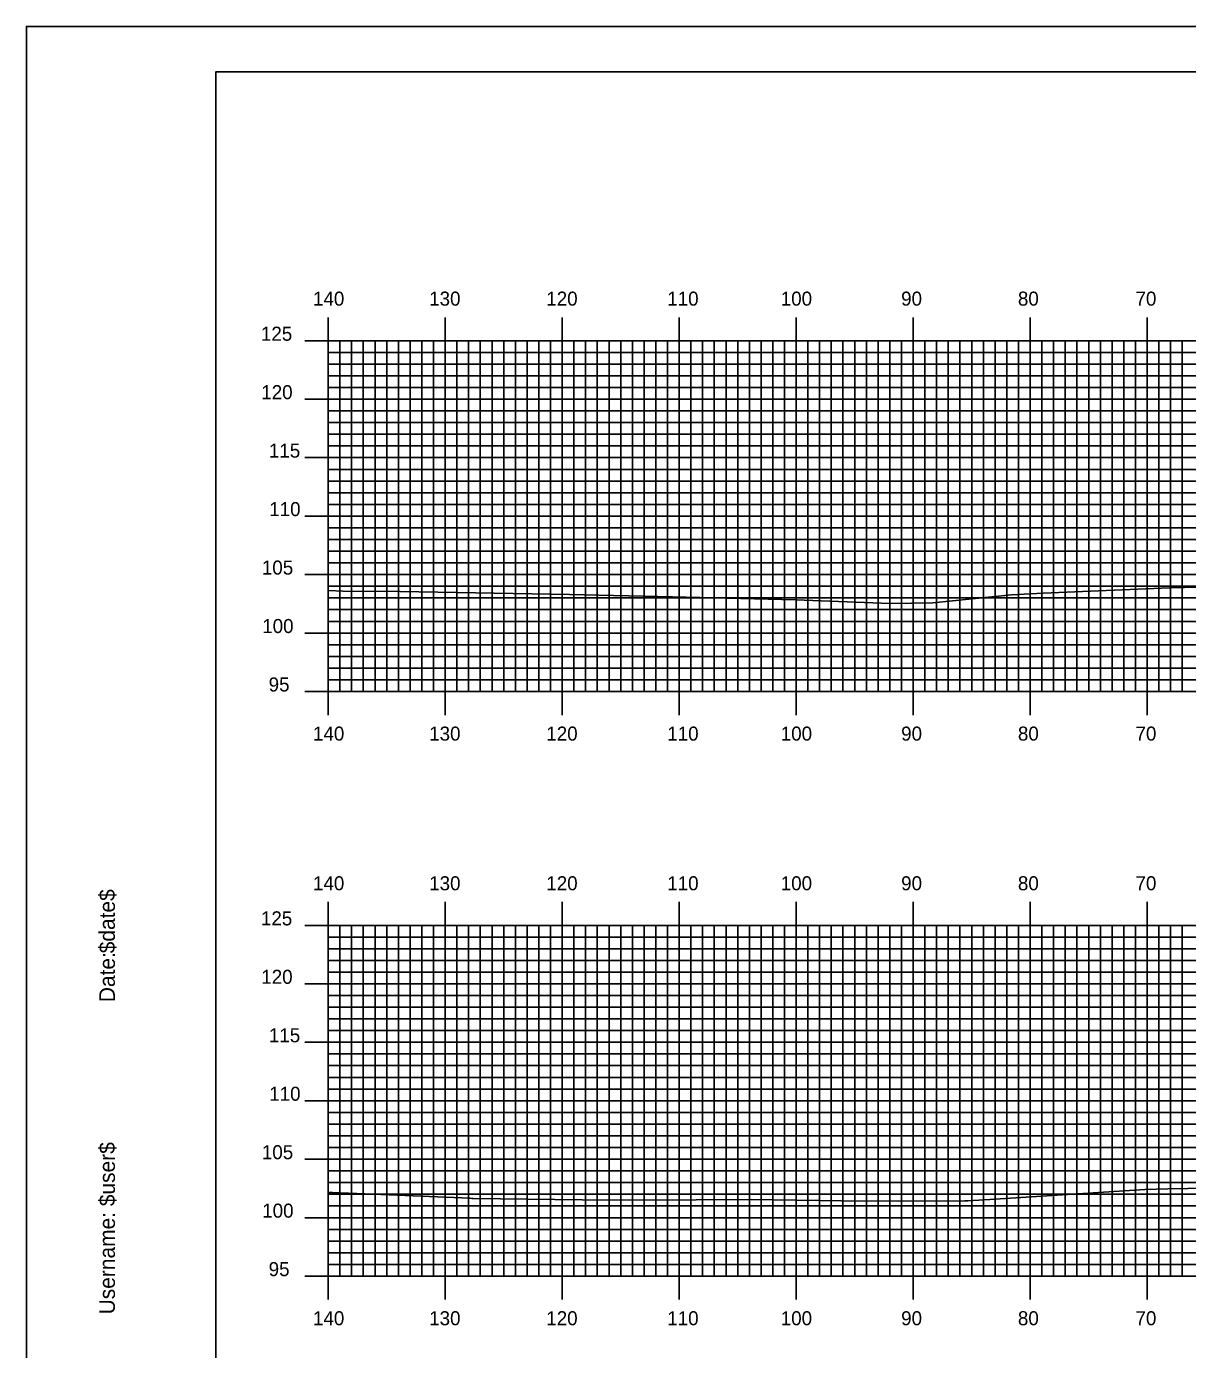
# Model space of a CAD drawing. Extents: x 1787763 to 1788106, y 442591 to 442811.
# Drawn here: x 1787762.8 to 1787862.1, y 442697.4 to 442810.5 of the extents above; entities that cross this region are included whole.
import ezdxf

# ---------------------------------------------------------------- set-up
doc = ezdxf.new("R2010")
doc.units = 0
for name, color, linetype in [('BORDER', 7, 'Continuous'), ('H_V ANNOTATION', 7, 'Continuous'), ('MAJOR', 7, 'Continuous'), ('MINOR', 7, 'Continuous'), ('PLOT BOUNDARY', 7, 'Continuous'), ('S_Roadway_Centerline', 7, 'Continuous')]:
    doc.layers.add(name, color=color, linetype=linetype)

msp = doc.modelspace()

# ---------------------------------------------------------------- linework, layer by layer
at = {"layer": 'BORDER'}
msp.add_lwpolyline([(1787779.02, 442596.67), (1788099.02, 442596.67), (1788099.02, 442806.67), (1787779.02, 442806.67)], close=True, dxfattribs=at)
at = {"layer": 'MAJOR'}
for p, q in [((1787788.62, 442785.67), (1787788.62, 442783.67)), ((1787798.62, 442785.67), (1787798.62, 442783.67)), ((1787808.62, 442785.67), (1787808.62, 442783.67)), ((1787818.62, 442785.67), (1787818.62, 442783.67)), ((1787828.62, 442785.67), (1787828.62, 442783.67)), ((1787838.62, 442785.67), (1787838.62, 442783.67)), ((1787848.62, 442785.67), (1787848.62, 442783.67)), ((1787858.62, 442785.67), (1787858.62, 442783.67)), ((1787786.61, 442783.67), (1787788.62, 442783.67)), ((1787788.62, 442783.67), (1788068.62, 442783.67)), ((1787788.62, 442753.67), (1787788.62, 442783.67)), ((1787788.62, 442753.67), (1787788.62, 442783.67)), ((1787788.62, 442783.67), (1788068.62, 442783.67)), ((1787798.62, 442753.67), (1787798.62, 442783.67)), ((1787808.62, 442753.67), (1787808.62, 442783.67)), ((1787818.62, 442753.67), (1787818.62, 442783.67)), ((1787828.62, 442753.67), (1787828.62, 442783.67)), ((1787838.62, 442753.67), (1787838.62, 442783.67)), ((1787848.62, 442753.67), (1787848.62, 442783.67)), ((1787858.62, 442753.67), (1787858.62, 442783.67)), ((1787786.61, 442778.67), (1787788.62, 442778.67)), ((1787788.62, 442778.67), (1788068.62, 442778.67)), ((1787786.61, 442773.67), (1787788.62, 442773.67)), ((1787788.62, 442773.67), (1788068.62, 442773.67)), ((1787786.61, 442768.67), (1787788.62, 442768.67)), ((1787788.62, 442768.67), (1788068.62, 442768.67)), ((1787786.61, 442763.67), (1787788.62, 442763.67)), ((1787788.62, 442763.67), (1788068.62, 442763.67)), ((1787786.61, 442758.67), (1787788.62, 442758.67)), ((1787788.62, 442758.67), (1788068.62, 442758.67)), ((1787786.61, 442753.67), (1787788.62, 442753.67)), ((1787788.62, 442753.67), (1788068.62, 442753.67)), ((1787788.62, 442753.67), (1788068.62, 442753.67)), ((1787788.62, 442751.66), (1787788.62, 442753.67)), ((1787798.62, 442751.66), (1787798.62, 442753.67)), ((1787808.62, 442751.66), (1787808.62, 442753.67)), ((1787818.62, 442751.66), (1787818.62, 442753.67)), ((1787828.62, 442751.66), (1787828.62, 442753.67)), ((1787838.62, 442751.66), (1787838.62, 442753.67)), ((1787848.62, 442751.66), (1787848.62, 442753.67)), ((1787858.62, 442751.66), (1787858.62, 442753.67)), ((1787788.62, 442735.67), (1787788.62, 442733.67)), ((1787798.62, 442735.67), (1787798.62, 442733.67)), ((1787808.62, 442735.67), (1787808.62, 442733.67)), ((1787818.62, 442735.67), (1787818.62, 442733.67)), ((1787828.62, 442735.67), (1787828.62, 442733.67)), ((1787838.62, 442735.67), (1787838.62, 442733.67)), ((1787848.62, 442735.67), (1787848.62, 442733.67)), ((1787858.62, 442735.67), (1787858.62, 442733.67)), ((1787786.61, 442733.67), (1787788.62, 442733.67)), ((1787788.62, 442733.67), (1788068.62, 442733.67)), ((1787788.62, 442703.67), (1787788.62, 442733.67)), ((1787788.62, 442703.67), (1787788.62, 442733.67)), ((1787788.62, 442733.67), (1788068.62, 442733.67)), ((1787798.62, 442703.67), (1787798.62, 442733.67)), ((1787808.62, 442703.67), (1787808.62, 442733.67)), ((1787818.62, 442703.67), (1787818.62, 442733.67)), ((1787828.62, 442703.67), (1787828.62, 442733.67)), ((1787838.62, 442703.67), (1787838.62, 442733.67)), ((1787848.62, 442703.67), (1787848.62, 442733.67)), ((1787858.62, 442703.67), (1787858.62, 442733.67)), ((1787786.61, 442728.67), (1787788.62, 442728.67)), ((1787788.62, 442728.67), (1788068.62, 442728.67)), ((1787786.61, 442723.67), (1787788.62, 442723.67)), ((1787788.62, 442723.67), (1788068.62, 442723.67)), ((1787786.61, 442718.67), (1787788.62, 442718.67)), ((1787788.62, 442718.67), (1788068.62, 442718.67)), ((1787786.61, 442713.67), (1787788.62, 442713.67)), ((1787788.62, 442713.67), (1788068.62, 442713.67)), ((1787786.61, 442708.67), (1787788.62, 442708.67)), ((1787788.62, 442708.67), (1788068.62, 442708.67)), ((1787786.61, 442703.67), (1787788.62, 442703.67)), ((1787788.62, 442703.67), (1788068.62, 442703.67)), ((1787788.62, 442703.67), (1788068.62, 442703.67)), ((1787788.62, 442701.66), (1787788.62, 442703.67)), ((1787798.62, 442701.66), (1787798.62, 442703.67)), ((1787808.62, 442701.66), (1787808.62, 442703.67)), ((1787818.62, 442701.66), (1787818.62, 442703.67)), ((1787828.62, 442701.66), (1787828.62, 442703.67)), ((1787838.62, 442701.66), (1787838.62, 442703.67)), ((1787848.62, 442701.66), (1787848.62, 442703.67)), ((1787858.62, 442701.66), (1787858.62, 442703.67))]:
    msp.add_line(p, q, dxfattribs=at)
at = {"layer": 'MINOR'}
for p, q in [((1787789.62, 442753.67), (1787789.62, 442783.67)), ((1787790.62, 442753.67), (1787790.62, 442783.67)), ((1787791.62, 442753.67), (1787791.62, 442783.67)), ((1787792.62, 442753.67), (1787792.62, 442783.67)), ((1787793.62, 442753.67), (1787793.62, 442783.67)), ((1787794.62, 442753.67), (1787794.62, 442783.67)), ((1787795.62, 442753.67), (1787795.62, 442783.67)), ((1787796.62, 442753.67), (1787796.62, 442783.67)), ((1787797.62, 442753.67), (1787797.62, 442783.67)), ((1787799.62, 442753.67), (1787799.62, 442783.67)), ((1787800.62, 442753.67), (1787800.62, 442783.67)), ((1787801.62, 442753.67), (1787801.62, 442783.67)), ((1787802.62, 442753.67), (1787802.62, 442783.67)), ((1787803.62, 442753.67), (1787803.62, 442783.67)), ((1787804.62, 442753.67), (1787804.62, 442783.67)), ((1787805.62, 442753.67), (1787805.62, 442783.67)), ((1787806.62, 442753.67), (1787806.62, 442783.67)), ((1787807.62, 442753.67), (1787807.62, 442783.67)), ((1787809.62, 442753.67), (1787809.62, 442783.67)), ((1787810.62, 442753.67), (1787810.62, 442783.67)), ((1787811.62, 442753.67), (1787811.62, 442783.67)), ((1787812.62, 442753.67), (1787812.62, 442783.67)), ((1787813.62, 442753.67), (1787813.62, 442783.67)), ((1787814.62, 442753.67), (1787814.62, 442783.67)), ((1787815.62, 442753.67), (1787815.62, 442783.67)), ((1787816.62, 442753.67), (1787816.62, 442783.67)), ((1787817.62, 442753.67), (1787817.62, 442783.67)), ((1787819.62, 442753.67), (1787819.62, 442783.67)), ((1787820.62, 442753.67), (1787820.62, 442783.67)), ((1787821.62, 442753.67), (1787821.62, 442783.67)), ((1787822.62, 442753.67), (1787822.62, 442783.67)), ((1787823.62, 442753.67), (1787823.62, 442783.67)), ((1787824.62, 442753.67), (1787824.62, 442783.67)), ((1787825.62, 442753.67), (1787825.62, 442783.67)), ((1787826.62, 442753.67), (1787826.62, 442783.67)), ((1787827.62, 442753.67), (1787827.62, 442783.67)), ((1787829.62, 442753.67), (1787829.62, 442783.67)), ((1787830.62, 442753.67), (1787830.62, 442783.67)), ((1787831.62, 442753.67), (1787831.62, 442783.67)), ((1787832.62, 442753.67), (1787832.62, 442783.67)), ((1787833.62, 442753.67), (1787833.62, 442783.67)), ((1787834.62, 442753.67), (1787834.62, 442783.67)), ((1787835.62, 442753.67), (1787835.62, 442783.67)), ((1787836.62, 442753.67), (1787836.62, 442783.67)), ((1787837.62, 442753.67), (1787837.62, 442783.67)), ((1787839.62, 442753.67), (1787839.62, 442783.67)), ((1787840.62, 442753.67), (1787840.62, 442783.67)), ((1787841.62, 442753.67), (1787841.62, 442783.67)), ((1787842.62, 442753.67), (1787842.62, 442783.67)), ((1787843.62, 442753.67), (1787843.62, 442783.67)), ((1787844.62, 442753.67), (1787844.62, 442783.67)), ((1787845.62, 442753.67), (1787845.62, 442783.67)), ((1787846.62, 442753.67), (1787846.62, 442783.67)), ((1787847.62, 442753.67), (1787847.62, 442783.67)), ((1787849.62, 442753.67), (1787849.62, 442783.67)), ((1787850.62, 442753.67), (1787850.62, 442783.67)), ((1787851.62, 442753.67), (1787851.62, 442783.67)), ((1787852.62, 442753.67), (1787852.62, 442783.67)), ((1787853.62, 442753.67), (1787853.62, 442783.67)), ((1787854.62, 442753.67), (1787854.62, 442783.67)), ((1787855.62, 442753.67), (1787855.62, 442783.67)), ((1787856.62, 442753.67), (1787856.62, 442783.67)), ((1787857.62, 442753.67), (1787857.62, 442783.67)), ((1787859.62, 442753.67), (1787859.62, 442783.67)), ((1787860.62, 442753.67), (1787860.62, 442783.67)), ((1787861.62, 442753.67), (1787861.62, 442783.67)), ((1787788.62, 442782.67), (1788068.62, 442782.67)), ((1787788.62, 442782.67), (1787790.62, 442782.67)), ((1787788.62, 442781.67), (1788068.62, 442781.67)), ((1787788.62, 442781.67), (1787790.62, 442781.67)), ((1787788.62, 442780.67), (1788068.62, 442780.67)), ((1787788.62, 442780.67), (1787790.62, 442780.67)), ((1787788.62, 442779.67), (1788068.62, 442779.67)), ((1787788.62, 442779.67), (1787790.62, 442779.67)), ((1787788.62, 442777.67), (1788068.62, 442777.67)), ((1787788.62, 442777.67), (1787790.62, 442777.67)), ((1787788.62, 442776.67), (1788068.62, 442776.67)), ((1787788.62, 442776.67), (1787790.62, 442776.67)), ((1787788.62, 442775.67), (1788068.62, 442775.67)), ((1787788.62, 442775.67), (1787790.62, 442775.67)), ((1787788.62, 442774.67), (1788068.62, 442774.67)), ((1787788.62, 442774.67), (1787790.62, 442774.67)), ((1787788.62, 442772.67), (1788068.62, 442772.67)), ((1787788.62, 442772.67), (1787790.62, 442772.67)), ((1787788.62, 442771.67), (1788068.62, 442771.67)), ((1787788.62, 442771.67), (1787790.62, 442771.67)), ((1787788.62, 442770.67), (1788068.62, 442770.67)), ((1787788.62, 442770.67), (1787790.62, 442770.67)), ((1787788.62, 442769.67), (1788068.62, 442769.67)), ((1787788.62, 442769.67), (1787790.62, 442769.67)), ((1787788.62, 442767.67), (1788068.62, 442767.67)), ((1787788.62, 442767.67), (1787790.62, 442767.67)), ((1787788.62, 442766.67), (1788068.62, 442766.67)), ((1787788.62, 442766.67), (1787790.62, 442766.67)), ((1787788.62, 442765.67), (1788068.62, 442765.67)), ((1787788.62, 442765.67), (1787790.62, 442765.67)), ((1787788.62, 442764.67), (1788068.62, 442764.67)), ((1787788.62, 442764.67), (1787790.62, 442764.67)), ((1787788.62, 442762.67), (1788068.62, 442762.67)), ((1787788.62, 442762.67), (1787790.62, 442762.67)), ((1787788.62, 442761.67), (1788068.62, 442761.67)), ((1787788.62, 442761.67), (1787790.62, 442761.67)), ((1787788.62, 442760.67), (1788068.62, 442760.67)), ((1787788.62, 442760.67), (1787790.62, 442760.67)), ((1787788.62, 442759.67), (1788068.62, 442759.67)), ((1787788.62, 442759.67), (1787790.62, 442759.67)), ((1787788.62, 442757.67), (1788068.62, 442757.67)), ((1787788.62, 442757.67), (1787790.62, 442757.67)), ((1787788.62, 442756.67), (1788068.62, 442756.67)), ((1787788.62, 442756.67), (1787790.62, 442756.67)), ((1787788.62, 442755.67), (1788068.62, 442755.67)), ((1787788.62, 442755.67), (1787790.62, 442755.67)), ((1787788.62, 442754.67), (1788068.62, 442754.67)), ((1787788.62, 442754.67), (1787790.62, 442754.67)), ((1787789.62, 442703.67), (1787789.62, 442733.67)), ((1787790.62, 442703.67), (1787790.62, 442733.67)), ((1787791.62, 442703.67), (1787791.62, 442733.67)), ((1787792.62, 442703.67), (1787792.62, 442733.67)), ((1787793.62, 442703.67), (1787793.62, 442733.67)), ((1787794.62, 442703.67), (1787794.62, 442733.67)), ((1787795.62, 442703.67), (1787795.62, 442733.67)), ((1787796.62, 442703.67), (1787796.62, 442733.67)), ((1787797.62, 442703.67), (1787797.62, 442733.67)), ((1787799.62, 442703.67), (1787799.62, 442733.67)), ((1787800.62, 442703.67), (1787800.62, 442733.67)), ((1787801.62, 442703.67), (1787801.62, 442733.67)), ((1787802.62, 442703.67), (1787802.62, 442733.67)), ((1787803.62, 442703.67), (1787803.62, 442733.67)), ((1787804.62, 442703.67), (1787804.62, 442733.67)), ((1787805.62, 442703.67), (1787805.62, 442733.67)), ((1787806.62, 442703.67), (1787806.62, 442733.67)), ((1787807.62, 442703.67), (1787807.62, 442733.67)), ((1787809.62, 442703.67), (1787809.62, 442733.67)), ((1787810.62, 442703.67), (1787810.62, 442733.67)), ((1787811.62, 442703.67), (1787811.62, 442733.67)), ((1787812.62, 442703.67), (1787812.62, 442733.67)), ((1787813.62, 442703.67), (1787813.62, 442733.67)), ((1787814.62, 442703.67), (1787814.62, 442733.67)), ((1787815.62, 442703.67), (1787815.62, 442733.67)), ((1787816.62, 442703.67), (1787816.62, 442733.67)), ((1787817.62, 442703.67), (1787817.62, 442733.67)), ((1787819.62, 442703.67), (1787819.62, 442733.67)), ((1787820.62, 442703.67), (1787820.62, 442733.67)), ((1787821.62, 442703.67), (1787821.62, 442733.67)), ((1787822.62, 442703.67), (1787822.62, 442733.67)), ((1787823.62, 442703.67), (1787823.62, 442733.67)), ((1787824.62, 442703.67), (1787824.62, 442733.67)), ((1787825.62, 442703.67), (1787825.62, 442733.67)), ((1787826.62, 442703.67), (1787826.62, 442733.67)), ((1787827.62, 442703.67), (1787827.62, 442733.67)), ((1787829.62, 442703.67), (1787829.62, 442733.67)), ((1787830.62, 442703.67), (1787830.62, 442733.67)), ((1787831.62, 442703.67), (1787831.62, 442733.67)), ((1787832.62, 442703.67), (1787832.62, 442733.67)), ((1787833.62, 442703.67), (1787833.62, 442733.67)), ((1787834.62, 442703.67), (1787834.62, 442733.67)), ((1787835.62, 442703.67), (1787835.62, 442733.67)), ((1787836.62, 442703.67), (1787836.62, 442733.67)), ((1787837.62, 442703.67), (1787837.62, 442733.67)), ((1787839.62, 442703.67), (1787839.62, 442733.67)), ((1787840.62, 442703.67), (1787840.62, 442733.67)), ((1787841.62, 442703.67), (1787841.62, 442733.67)), ((1787842.62, 442703.67), (1787842.62, 442733.67)), ((1787843.62, 442703.67), (1787843.62, 442733.67)), ((1787844.62, 442703.67), (1787844.62, 442733.67)), ((1787845.62, 442703.67), (1787845.62, 442733.67)), ((1787846.62, 442703.67), (1787846.62, 442733.67)), ((1787847.62, 442703.67), (1787847.62, 442733.67)), ((1787849.62, 442703.67), (1787849.62, 442733.67)), ((1787850.62, 442703.67), (1787850.62, 442733.67)), ((1787851.62, 442703.67), (1787851.62, 442733.67)), ((1787852.62, 442703.67), (1787852.62, 442733.67)), ((1787853.62, 442703.67), (1787853.62, 442733.67)), ((1787854.62, 442703.67), (1787854.62, 442733.67)), ((1787855.62, 442703.67), (1787855.62, 442733.67)), ((1787856.62, 442703.67), (1787856.62, 442733.67)), ((1787857.62, 442703.67), (1787857.62, 442733.67)), ((1787859.62, 442703.67), (1787859.62, 442733.67)), ((1787860.62, 442703.67), (1787860.62, 442733.67)), ((1787861.62, 442703.67), (1787861.62, 442733.67)), ((1787788.62, 442732.67), (1788068.62, 442732.67)), ((1787788.62, 442732.67), (1787790.62, 442732.67)), ((1787788.62, 442731.67), (1788068.62, 442731.67)), ((1787788.62, 442731.67), (1787790.62, 442731.67)), ((1787788.62, 442730.67), (1788068.62, 442730.67)), ((1787788.62, 442730.67), (1787790.62, 442730.67)), ((1787788.62, 442729.67), (1788068.62, 442729.67)), ((1787788.62, 442729.67), (1787790.62, 442729.67)), ((1787788.62, 442727.67), (1788068.62, 442727.67)), ((1787788.62, 442727.67), (1787790.62, 442727.67)), ((1787788.62, 442726.67), (1788068.62, 442726.67)), ((1787788.62, 442726.67), (1787790.62, 442726.67)), ((1787788.62, 442725.67), (1788068.62, 442725.67)), ((1787788.62, 442725.67), (1787790.62, 442725.67)), ((1787788.62, 442724.67), (1788068.62, 442724.67)), ((1787788.62, 442724.67), (1787790.62, 442724.67)), ((1787788.62, 442722.67), (1788068.62, 442722.67)), ((1787788.62, 442722.67), (1787790.62, 442722.67)), ((1787788.62, 442721.67), (1788068.62, 442721.67)), ((1787788.62, 442721.67), (1787790.62, 442721.67)), ((1787788.62, 442720.67), (1788068.62, 442720.67)), ((1787788.62, 442720.67), (1787790.62, 442720.67)), ((1787788.62, 442719.67), (1788068.62, 442719.67)), ((1787788.62, 442719.67), (1787790.62, 442719.67)), ((1787788.62, 442717.67), (1788068.62, 442717.67)), ((1787788.62, 442717.67), (1787790.62, 442717.67)), ((1787788.62, 442716.67), (1788068.62, 442716.67)), ((1787788.62, 442716.67), (1787790.62, 442716.67)), ((1787788.62, 442715.67), (1788068.62, 442715.67)), ((1787788.62, 442715.67), (1787790.62, 442715.67)), ((1787788.62, 442714.67), (1788068.62, 442714.67)), ((1787788.62, 442714.67), (1787790.62, 442714.67)), ((1787788.62, 442712.67), (1788068.62, 442712.67)), ((1787788.62, 442712.67), (1787790.62, 442712.67)), ((1787788.62, 442711.67), (1788068.62, 442711.67)), ((1787788.62, 442711.67), (1787790.62, 442711.67)), ((1787788.62, 442710.67), (1788068.62, 442710.67)), ((1787788.62, 442710.67), (1787790.62, 442710.67)), ((1787788.62, 442709.67), (1788068.62, 442709.67)), ((1787788.62, 442709.67), (1787790.62, 442709.67)), ((1787788.62, 442707.67), (1788068.62, 442707.67)), ((1787788.62, 442707.67), (1787790.62, 442707.67)), ((1787788.62, 442706.67), (1788068.62, 442706.67)), ((1787788.62, 442706.67), (1787790.62, 442706.67)), ((1787788.62, 442705.67), (1788068.62, 442705.67)), ((1787788.62, 442705.67), (1787790.62, 442705.67)), ((1787788.62, 442704.67), (1788068.62, 442704.67)), ((1787788.62, 442704.67), (1787790.62, 442704.67))]:
    msp.add_line(p, q, dxfattribs=at)
at = {"layer": 'PLOT BOUNDARY'}
msp.add_lwpolyline([(1787762.83, 442590.55), (1788102.83, 442590.55), (1788102.83, 442810.55), (1787762.83, 442810.55)], close=True, dxfattribs=at)
at = {"layer": 'S_Roadway_Centerline'}
for points in [[(1787788.62, 442762.31), (1787788.65, 442762.31), (1787789.88, 442762.26), (1787794.77, 442762.21), (1787809.24, 442761.97), (1787818.04, 442761.78), (1787828.57, 442761.5), (1787836.65, 442761.2), (1787840.31, 442761.25), (1787847.03, 442761.93), (1787849.73, 442762.08), (1787860.53, 442762.53), (1787866.88, 442762.69)], [(1787788.62, 442710.81), (1787788.98, 442710.82), (1787800.72, 442710.33), (1787800.89, 442710.32), (1787801, 442710.32), (1787812.65, 442710.16), (1787820.08, 442710.19), (1787824.77, 442710.22), (1787832.46, 442710.12), (1787837.38, 442710.07), (1787843.03, 442710.1), (1787843.25, 442710.1), (1787843.29, 442710.11), (1787845.64, 442710.24), (1787858.41, 442711.08), (1787860.39, 442711.13), (1787863.81, 442711.2)]]:
    msp.add_lwpolyline(points, dxfattribs=at)

# ---------------------------------------------------------------- texts
at = {"layer": 'BORDER'}
for s, p in [('$date$', (1787770.39, 442731.28)), ('Date:', (1787770.39, 442727.1)), ('$user$', (1787770.39, 442709.65)), ('Username:', (1787770.39, 442700.4))]:
    msp.add_text(s, height=1.339, rotation=90, dxfattribs=at).set_placement(p)
at = {"layer": 'H_V ANNOTATION'}
for s, p in [('140', (1787787.32, 442786.67)), ('130', (1787797.25, 442786.67)), ('120', (1787807.26, 442786.67)), ('110', (1787817.6, 442786.67)), ('100', (1787827.3, 442786.67)), ('90', (1787837.59, 442786.67)), ('80', (1787847.57, 442786.67)), ('70', (1787857.62, 442786.67)), ('125', (1787782.87, 442783.67)), ('120', (1787782.9, 442778.67)), ('115', (1787783.55, 442773.67)), ('110', (1787783.58, 442768.67)), ('105', (1787782.95, 442763.67)), ('100', (1787782.98, 442758.67)), ('95', (1787783.53, 442753.67)), ('140', (1787787.32, 442749.47)), ('130', (1787797.25, 442749.47)), ('120', (1787807.26, 442749.47)), ('110', (1787817.6, 442749.47)), ('100', (1787827.3, 442749.47)), ('90', (1787837.59, 442749.47)), ('80', (1787847.57, 442749.47)), ('70', (1787857.62, 442749.47)), ('140', (1787787.32, 442736.67)), ('130', (1787797.25, 442736.67)), ('120', (1787807.26, 442736.67)), ('110', (1787817.6, 442736.67)), ('100', (1787827.3, 442736.67)), ('90', (1787837.59, 442736.67)), ('80', (1787847.57, 442736.67)), ('70', (1787857.62, 442736.67)), ('125', (1787782.87, 442733.67)), ('120', (1787782.9, 442728.67)), ('115', (1787783.55, 442723.67)), ('110', (1787783.58, 442718.67)), ('105', (1787782.95, 442713.67)), ('100', (1787782.98, 442708.67)), ('95', (1787783.53, 442703.67)), ('140', (1787787.32, 442699.47)), ('130', (1787797.25, 442699.47)), ('120', (1787807.26, 442699.47)), ('110', (1787817.6, 442699.47)), ('100', (1787827.3, 442699.47)), ('90', (1787837.59, 442699.47)), ('80', (1787847.57, 442699.47)), ('70', (1787857.62, 442699.47))]:
    msp.add_text(s, height=1.2, dxfattribs=at).set_placement(p)
at = {"layer": 'MAJOR'}
for p in [(1787788.61, 442753.67), (1787788.61, 442703.67)]:
    msp.add_text('-', height=0.012, dxfattribs=at).set_placement(p)

doc.saveas('drawing.dxf')
